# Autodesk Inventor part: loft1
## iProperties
Author: Administrator
Created: 2000-12
Part Number: loft1
Document SubType Name: Modeling
Designer: Administrator
Control State: 0
Master: False
Checked Out: False
PropertySet Name: Design Tracking Control
Shininess: 0.0
PropertySet Name: _Private Model Information
Density: 0.0
Volumn: 0.0
Area: 0.0
PropertySet Name: Model Information
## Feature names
1. Loft1
